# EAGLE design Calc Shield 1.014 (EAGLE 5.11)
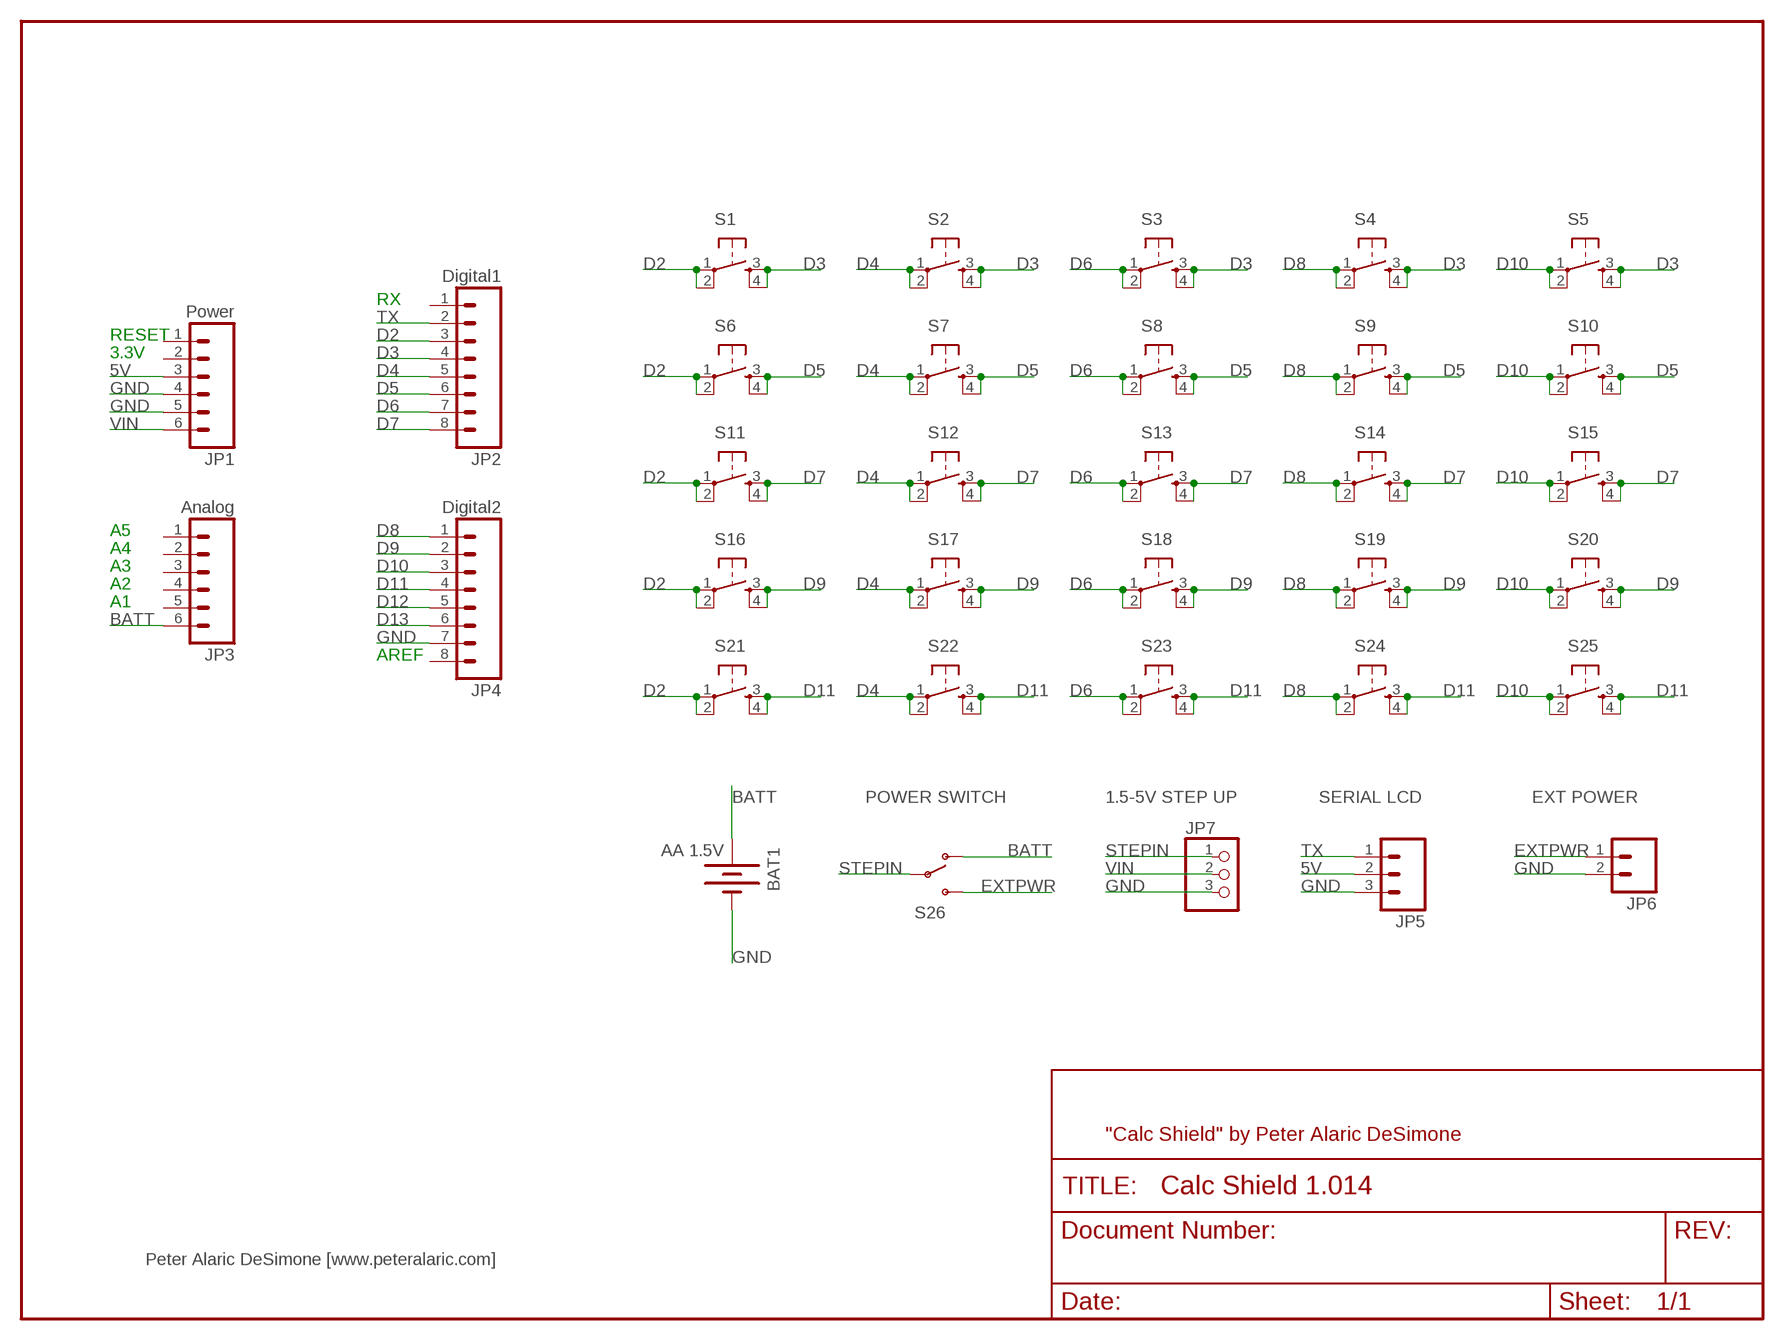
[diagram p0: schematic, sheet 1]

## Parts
BAT1  BATTERYAA  [BATTERY-AA]
JP1  Power  M06SIP  [1X06]
JP2  Digital1  M08  [1X08]
JP3  Analog  M06SIP  [1X06]
JP4  Digital2  M08  [1X08]
JP5  M03POLAR_LOCK  [MOLEX-1X3_LOCK]
JP6  M02POLAR_LOCK  [MOLEX-1X2_LOCK]
JP7  PINHD-1X3  [1X03]
S1  TAC_SWITCHPTH  [TACTILE-PTH]
S2  TAC_SWITCHPTH  [TACTILE-PTH]
S3  TAC_SWITCHPTH  [TACTILE-PTH]
S4  TAC_SWITCHPTH  [TACTILE-PTH]
S5  TAC_SWITCHPTH  [TACTILE-PTH]
S6  TAC_SWITCHPTH  [TACTILE-PTH]
S7  TAC_SWITCHPTH  [TACTILE-PTH]
S8  TAC_SWITCHPTH  [TACTILE-PTH]
S9  TAC_SWITCHPTH  [TACTILE-PTH]
S10  TAC_SWITCHPTH  [TACTILE-PTH]
S11  TAC_SWITCHPTH  [TACTILE-PTH]
S12  TAC_SWITCHPTH  [TACTILE-PTH]
S13  TAC_SWITCHPTH  [TACTILE-PTH]
S14  TAC_SWITCHPTH  [TACTILE-PTH]
S15  TAC_SWITCHPTH  [TACTILE-PTH]
S16  TAC_SWITCHPTH  [TACTILE-PTH]
S17  TAC_SWITCHPTH  [TACTILE-PTH]
S18  TAC_SWITCHPTH  [TACTILE-PTH]
S19  TAC_SWITCHPTH  [TACTILE-PTH]
S20  TAC_SWITCHPTH  [TACTILE-PTH]
S21  TAC_SWITCHPTH  [TACTILE-PTH]
S22  TAC_SWITCHPTH  [TACTILE-PTH]
S23  TAC_SWITCHPTH  [TACTILE-PTH]
S24  TAC_SWITCHPTH  [TACTILE-PTH]
S25  TAC_SWITCHPTH  [TACTILE-PTH]
S26  SWITCH-SPSTPTH_LOCK  [SWITCH-SPDT_LOCK.007S]

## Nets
5V: JP1.3 JP5.2
BATT: BAT1.PWR@1(+) JP3.6 S26.1(O)
D2: JP2.3 S1.1 S1.2 S6.1 S6.2 S11.1 S11.2 S16.1 S16.2 S21.1 S21.2
D3: JP2.4 S1.3 S1.4 S2.3 S2.4 S3.3 S3.4 S4.3 S4.4 S5.3 S5.4
D4: JP2.5 S2.1 S2.2 S7.1 S7.2 S12.1 S12.2 S17.1 S17.2 S22.1 S22.2
D5: JP2.6 S6.3 S6.4 S7.3 S7.4 S8.3 S8.4 S9.3 S9.4 S10.3 S10.4
D6: JP2.7 S3.1 S3.2 S8.1 S8.2 S13.1 S13.2 S18.1 S18.2 S23.1 S23.2
D7: JP2.8 S11.3 S11.4 S12.3 S12.4 S13.3 S13.4 S14.3 S14.4 S15.3 S15.4
D8: JP4.1 S4.1 S4.2 S9.1 S9.2 S14.1 S14.2 S19.1 S19.2 S24.1 S24.2
D9: JP4.2 S16.3 S16.4 S17.3 S17.4 S18.3 S18.4 S19.3 S19.4 S20.3 S20.4
D10: JP4.3 S5.1 S5.2 S10.1 S10.2 S15.1 S15.2 S20.1 S20.2 S25.1 S25.2
D11: JP4.4 S21.3 S21.4 S22.3 S22.4 S23.3 S23.4 S24.3 S24.4 S25.3 S25.4
D12: JP4.5
D13: JP4.6
EXTPWR: JP6.1 S26.3(S)
GND: BAT1.GND@1(-) JP1.4 JP1.5 JP4.7 JP5.3 JP6.2 JP7.3
STEPIN: JP7.1 S26.2(P)
TX: JP2.2 JP5.1
VIN: JP1.6 JP7.2
Unconnected: JP1.1 JP1.2 JP2.1 JP3.1 JP3.2 JP3.3 JP3.4 JP3.5 JP4.8

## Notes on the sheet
- RX
- RESET
- 3.3V
- A5
- A4
- A3
- A2
- A1
- AREF
- POWER SWITCH | 1.5-5V STEP UP | SERIAL LCD | EXT POWER
- AA 1.5V
- "Calc Shield" by Peter Alaric DeSimone
- Peter Alaric DeSimone [www.peteralaric.com]

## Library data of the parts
BAT1 = SparkFun:BATTERY: Battery Holders
JP1 JP3 = SparkFun:M06: Header 6 Standard 6-pin 0.1" header. Use with straight break away headers (SKU : PRT-00116), right angle break away headers (PRT-00553), swiss pins (PRT-00743), machine pins (PRT-00117), and female headers (PRT-00115). Molex polarized connector foot print use with SKU : PRT-08094 with associated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
JP2 JP4 = SparkFun:M08: Header 8 Standard 8-pin 0.1" header. Use with straight break away headers (SKU : PRT-00116), right angle break away headers (PRT-00553), swiss pins (PRT-00743), machine pins (PRT-00117), and female headers (PRT-00115).
JP5 = SparkFun:M03: Header 3 Standard 3-pin 0.1" header. Use with straight break away headers (SKU : PRT-00116), right angle break away headers (PRT-00553), swiss pins (PRT-00743), machine pins (PRT-00117), and female headers (PRT-00115). Molex polarized connector foot print use with SKU : PRT-08232 with associated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
JP6 = SparkFun:M02: Header 2
JP7 = pinhead:PINHD-1X3: PIN HEADER
S1-S25 = SparkFun:TAC_SWITCH: Momentary Switch Button commonly used for reset or general input. Spark Fun Electronics SKU : COM-00097
S26 = SparkFun:SWITCH-SPST: SPST Switch Simple slide switch. Spark Fun Electronics SKU : COM-00102

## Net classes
1 power: width 0.254 mm

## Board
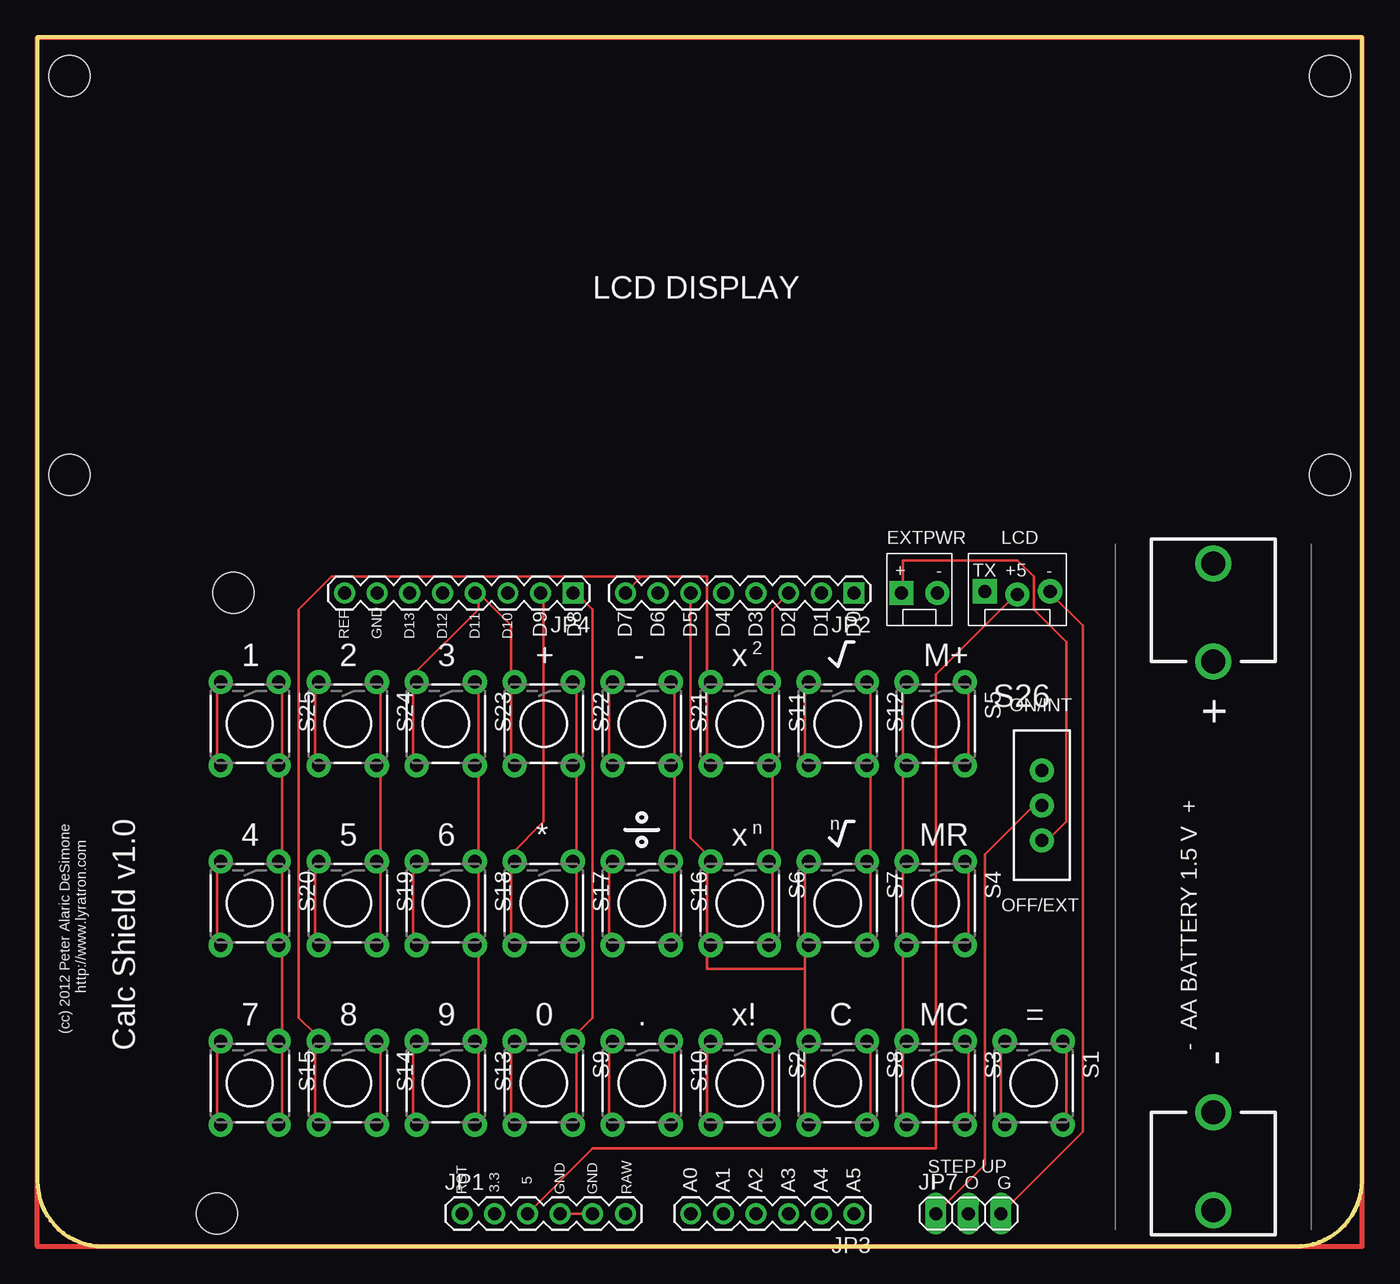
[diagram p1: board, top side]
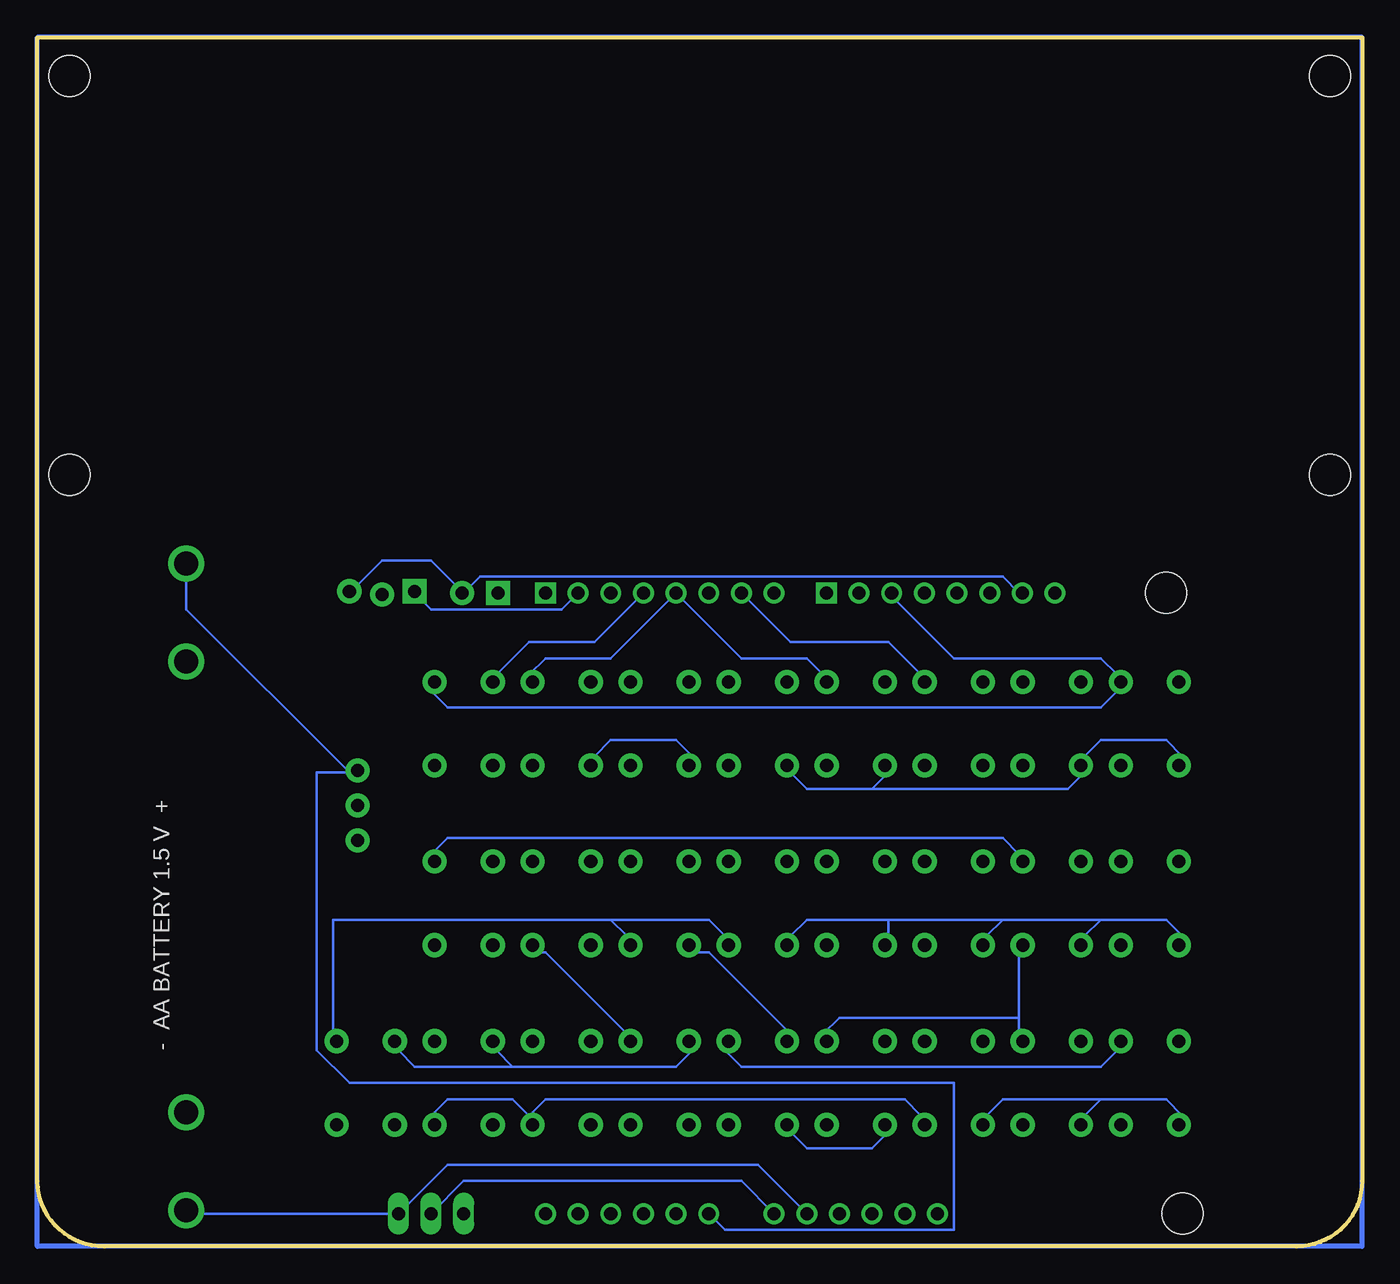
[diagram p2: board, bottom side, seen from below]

Size 103 x 94 mm. Coordinates in mm from the lower left corner, seen from the top.
Outline: 97.79,0 arc90 103,5.08 103,94 0,94 0,5.08 arc90 5.08,0 97.79,0
Copper layers (1*16): Top 0.035mm / dielectric 1.5mm / Bottom 0.035mm
Design rules "SparkFun": minimum track width 8mil, minimum drill 20mil, track to track 8mil, track to pad 8mil, pad to pad 8mil, via to via 8mil, smd to smd 8mil, copper to edge 10mil, drill to drill 8mil, minimum pad ring 12mil, minimum via ring 10mil, stop-mask expansion 4mil, vias tented up to drill 20mil, thermal gap 10mil
Holes 3.2 mm at 15.24,50.8 13.97,2.54 2.5,91 100.5,91 100.5,60 2.5,60

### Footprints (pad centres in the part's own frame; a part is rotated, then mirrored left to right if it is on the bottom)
BATTERY-AA = drill 1.854 round: GND@1 25.146,0; GND@2 17.526,0; PWR@1 -25.146,0; PWR@2 -17.526,0
1X06 = drill 1.016 round: 1 0,0; 2 2.54,0; 3 5.08,0; 4 7.62,0; 5 10.16,0; 6 12.7,0
1X08 = drill 1.016 square: 1 0,0 | drill 1.016 round: 2 2.54,0; 3 5.08,0; 4 7.62,0; 5 10.16,0; 6 12.7,0; 7 15.24,0; 8 17.78,0
MOLEX-1X3_LOCK = drill 1.016 pad 1.88 square: 1 0,0.127 | drill 1.016 pad 1.88 round: 2 2.54,-0.127; 3 5.08,0.127
MOLEX-1X2_LOCK = drill 1.016 pad 1.88 square: 1 -0.127,0 | drill 1.016 pad 1.88 round: 2 2.667,0
1X03 = drill 1.016 long: 1 -2.54,0; 2 0,0; 3 2.54,0
TACTILE-PTH = drill 1.016 pad 1.88 round: 1 -3.251,2.261; 2 3.251,2.261; 3 -3.251,-2.261; 4 3.251,-2.261
SWITCH-SPDT_LOCK.007S = drill 1.016 pad 1.88 round: 1 0,2.718; 2 0,0; 3 0,-2.718

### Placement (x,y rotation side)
BAT1  91.44,27.94 270 top
JP1  33.02,2.54 0 top
JP2  63.5,50.8 180 top
JP3  63.5,2.54 180 top
JP4  41.66,50.8 180 top
JP5  73.66,50.8 0 top
JP6  67.31,50.8 0 top
JP7  72.39,2.54 0 top
S1  77.47,12.7 270 top
S2  54.61,12.7 270 top
S3  69.85,12.7 270 top
S4  69.85,26.67 270 top
S5  69.85,40.64 270 top
S6  54.61,26.67 270 top
S7  62.23,26.67 270 top
S8  62.23,12.7 270 top
S9  39.37,12.7 270 top
S10  46.99,12.7 270 top
S11  54.61,40.64 270 top
S12  62.23,40.64 270 top
S13  31.75,12.7 270 top
S14  24.13,12.7 270 top
S15  16.51,12.7 270 top
S16  46.99,26.67 270 top
S17  39.37,26.67 270 top
S18  31.75,26.67 270 top
S19  24.13,26.67 270 top
S20  16.51,26.67 270 top
S21  46.99,40.64 270 top
S22  39.37,40.64 270 top
S23  31.75,40.64 270 top
S24  24.13,40.64 270 top
S25  16.51,40.64 270 top
S26  78.11,34.29 0 top

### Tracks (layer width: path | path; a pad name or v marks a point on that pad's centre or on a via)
5V
  Top 0.203: JP1.3 43.18,7.62 69.85,7.62 69.85,44.45 76.2,50.8 JP5.2
BATT
  Bottom 0.203: 78.74,36.83 91.44,49.53 BAT1.PWR@1 | JP3.6 49.53,1.27 31.75,1.27 31.75,12.7 78.74,12.7 81.28,15.24 81.28,36.83 78.74,36.83 | 78.74,36.83 S26.1
D2
  Top 0.203: S16.2 49.53,24.13 49.53,29.21 S16.1 49.53,30.48 49.53,36.83 S21.2 49.53,38.1 49.53,43.18 S21.1 | S1.2 80.01,10.16 80.01,15.24 S1.1 | S6.2 57.15,24.13 57.15,29.21 S6.1 57.15,30.48 57.15,36.83 S11.2 57.15,38.1 57.15,43.18 S11.1 57.15,44.45 57.15,49.53 JP2.3
  Bottom 0.203: 58.42,25.4 80.01,25.4 80.01,16.51 S1.1 | 58.42,25.4 57.15,24.13 S6.2 | 58.42,25.4 50.8,25.4 49.53,24.13 S16.2
D3
  Top 0.203: S5.3 67.31,43.18 67.31,38.1 S5.4 67.31,36.83 67.31,30.48 S4.3 67.31,29.21 67.31,24.13 S4.4 67.31,22.86 67.31,16.51 S3.3 67.31,15.24 67.31,10.16 S3.4 | S1.4 74.93,10.16 74.93,15.24 S1.3 | S2.4 52.07,10.16 52.07,15.24 S2.3
  Bottom 0.203: JP2.4 59.69,46.99 64.77,46.99 67.31,44.45 S5.3 | 66.04,13.97 53.34,13.97 52.07,15.24 S2.3 | 66.04,13.97 67.31,15.24 S3.3 | 66.04,13.97 73.66,13.97 74.93,15.24 S1.3
D4
  Top 0.203: S17.2 41.91,24.13 41.91,29.21 S17.1 41.91,30.48 41.91,36.83 S22.2 41.91,38.1 41.91,43.18 S22.1 | S12.1 64.77,43.18 64.77,38.1 S12.2 64.77,36.83 64.77,30.48 S7.1 64.77,29.21 64.77,24.13 S7.2 | S2.2 57.15,10.16 57.15,15.24 S2.1
  Bottom 0.203: S22.1 41.91,44.45 43.18,45.72 48.26,45.72 JP2.5 58.42,45.72 63.5,45.72 64.77,44.45 S12.1 | S2.1 57.15,16.51 63.5,22.86 64.77,22.86 S7.2
D5
  Top 0.203: S8.4 59.69,10.16 59.69,15.24 S8.3 59.69,16.51 59.69,21.59 | S7.3 59.69,29.21 59.69,24.13 S7.4 59.69,22.86 59.69,21.59 | S9.4 36.83,10.16 36.83,15.24 S9.3 | S10.4 44.45,10.16 44.45,15.24 S10.3 | JP2.6 50.8,31.75 52.07,30.48 S6.3 52.07,29.21 52.07,24.13 S6.4 52.07,22.86 52.07,21.59 59.69,21.59
  Bottom 0.203: S9.4 36.83,8.89 38.1,7.62 43.18,7.62 44.45,8.89 S10.4 | S10.3 44.45,16.51 50.8,22.86 52.07,22.86 S6.4
D6
  Top 0.203: S23.1 34.29,43.18 34.29,38.1 S23.2 34.29,36.83 34.29,30.48 S18.1 34.29,29.21 34.29,24.13 S18.2 34.29,22.86 34.29,16.51 S13.1 34.29,15.24 34.29,10.16 S13.2 | S8.2 64.77,10.16 64.77,15.24 S8.1 | S3.2 72.39,10.16 72.39,15.24 S3.1
  Bottom 0.203: JP2.7 44.45,46.99 36.83,46.99 34.29,44.45 S23.1 | 64.77,10.16 66.04,11.43 71.12,11.43 72.39,10.16 S3.2 | 64.77,10.16 63.5,11.43 35.56,11.43 34.29,10.16 S13.2 | 64.77,10.16 S8.2
D7
  Top 0.203: S13.4 29.21,10.16 29.21,15.24 S13.3 | S15.4 13.97,10.16 13.97,15.24 S15.3 | S14.4 21.59,10.16 21.59,15.24 S14.3 21.59,16.51 20.32,17.78 20.32,49.53 22.86,52.07 46.99,52.07 | S12.4 59.69,38.1 59.69,43.18 S12.3 | 46.99,52.07 JP2.8 | 46.99,52.07 52.07,52.07 52.07,44.45 S11.3 52.07,43.18 52.07,38.1 S11.4
  Bottom 0.203: 20.32,11.43 15.24,11.43 13.97,10.16 S15.4 | 20.32,11.43 21.59,10.16 S14.4 | 20.32,11.43 27.94,11.43 29.21,10.16 S13.4 | S12.4 59.69,38.1 58.42,39.37 53.34,39.37 52.07,38.1 S11.4
D8
  Top 0.203: JP4.1 41.91,50.8 43.18,49.53 43.18,17.78 41.91,16.51 S9.1 41.91,15.24 41.91,10.16 S9.2 | S24.1 26.67,43.18 26.67,38.1 S24.2 26.67,36.83 26.67,30.48 S19.1 26.67,29.21 26.67,24.13 S19.2 | S4.2 72.39,24.13 72.39,29.21 S4.1 | S14.2 26.67,10.16 26.67,15.24 S14.1
  Bottom 0.203: 26.67,17.78 26.67,22.86 S19.2 | 26.67,17.78 26.67,16.51 S14.1 | S4.1 72.39,30.48 71.12,31.75 27.94,31.75 26.67,30.48 S19.1 | 26.67,17.78 40.64,17.78 41.91,16.51 S9.1
D9
  Top 0.203: JP4.2 39.37,50.8 39.37,33.02 36.83,30.48 S17.3 36.83,29.21 36.83,24.13 S17.4 | S16.4 44.45,24.13 44.45,29.21 S16.3 | S18.4 29.21,24.13 29.21,29.21 S18.3 | S20.4 13.97,24.13 13.97,29.21 S20.3 | S19.4 21.59,24.13 21.59,29.21 S19.3
  Bottom 0.203: 20.32,25.4 15.24,25.4 13.97,24.13 S20.4 | 20.32,25.4 21.59,24.13 S19.4 | 27.94,25.4 29.21,24.13 S18.4 | 20.32,25.4 27.94,25.4 | 27.94,25.4 36.83,25.4 | 36.83,25.4 43.18,25.4 44.45,24.13 S16.4 | 36.83,25.4 36.83,24.13 S17.4
D10
  Top 0.203: S10.2 49.53,10.16 49.53,15.24 S10.1 | S15.2 19.05,10.16 19.05,15.24 S15.1 19.05,16.51 19.05,22.86 S20.2 19.05,24.13 19.05,29.21 S20.1 19.05,30.48 19.05,36.83 S25.2 19.05,38.1 19.05,43.18 S25.1 | S5.2 72.39,38.1 72.39,43.18 S5.1
  Bottom 0.203: S10.1 49.53,15.24 48.26,13.97 20.32,13.97 19.05,15.24 S15.1 | JP4.3 36.83,50.8 31.75,45.72 20.32,45.72 19.05,44.45 S25.1 19.05,43.18 20.32,41.91 71.12,41.91 72.39,43.18 S5.1
D11
  Top 0.203: S25.4 13.97,38.1 13.97,43.18 S25.3 | S24.4 21.59,38.1 21.59,43.18 S24.3 | S21.4 44.45,38.1 44.45,43.18 S21.3 | S23.4 29.21,38.1 29.21,43.18 S23.3 29.21,44.45 34.29,49.53 34.29,50.8 | 34.29,50.8 36.83,48.26 36.83,44.45 S22.3 36.83,43.18 36.83,38.1 S22.4 | 34.29,50.8 JP4.4
  Bottom 0.203: S25.4 13.97,38.1 15.24,39.37 20.32,39.37 21.59,38.1 S24.4 21.59,36.83 22.86,35.56 38.1,35.56 | 38.1,35.56 43.18,35.56 44.45,36.83 S21.4 | 38.1,35.56 36.83,36.83 S22.4
EXTPWR
  Top 0.203: S26.3 78.74,31.75 80.01,33.02 80.01,46.99 77.47,49.53 77.47,52.07 76.2,53.34 67.31,53.34 67.31,50.8 JP6.1
GND
  Top 0.203: JP1.4 JP1.5 | JP7.3 81.28,8.89 81.28,48.26 78.74,50.8 JP5.3
  Bottom 0.203: 69.85,50.8 68.58,52.07 27.94,52.07 26.67,50.8 JP4.7 | 69.85,50.8 72.39,53.34 76.2,53.34 78.74,50.8 JP5.3 | 69.85,50.8 JP6.2 | BAT1.GND@1 91.44,2.54 JP7.3 71.12,6.35 46.99,6.35 JP1.5
N$1
  Top 0.406: 0,0 0,94 103,94 103,0 0,0
N$2
  Bottom 0.406: 0,0 0,94 103,94 103,0 0,0
STEPIN
  Top 0.203: JP7.1 73.66,6.35 73.66,30.48 77.47,34.29 S26.2
TX
  Bottom 0.203: JP2.2 62.23,49.53 72.39,49.53 73.66,50.8 JP5.1
VIN
  Bottom 0.203: JP1.6 48.26,5.08 69.85,5.08 JP7.2

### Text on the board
tPlace: REF | GND | D13 | D12 | D11 | D10 | D9 | D8 | D7 | D6 | D5 | D4 | D3 | D2 | D1 | D0 | 5 | RST | 3.3 | GND | GND | RAW | A0 | A1 | A2 | A3 | A4 | A5
_tsilk: LCD DISPLAY | EXTPWR | LCD | + | - | TX | +5 | - | 2 | 1 | 2 | 3 | + | - | x | M+ | ON/INT | n | n | 4 | 5 | 6 | * | x | MR | OFF/EXT | http://www.lyratron.com | (cc) 2012 Peter Alaric DeSimone | 7 | 8 | 9 | 0 | . | x! | C | MC | = | Calc Shield v1.0 | - AA BATTERY 1.5 V + | STEP UP | I | O | G
_bsilk: - AA BATTERY 1.5 V +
